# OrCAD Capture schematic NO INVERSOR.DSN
size A
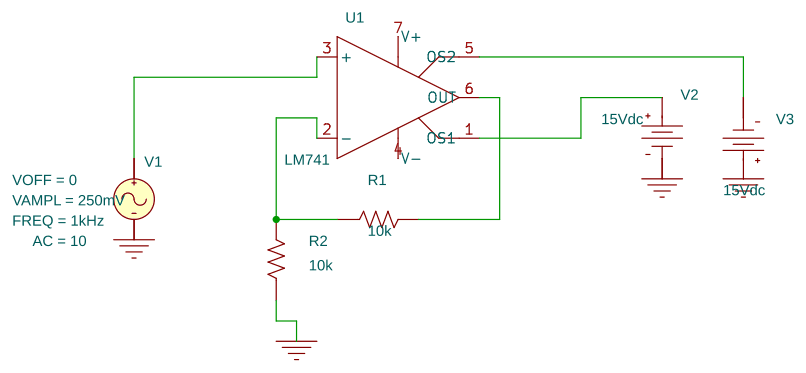
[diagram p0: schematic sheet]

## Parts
R1  10k  [AX/RC05]
R2  10k  [AX/RC05]
U1  LM741  [DIP.100/8/W.300/L.450]
V1  VSIN
V2  VDC
V3  VDC

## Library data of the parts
R1 R2 = r
U1 = LM741
V1 = VSIN: AC: 10; FREQ: 1kHz; VAMPL: 250mV; VOFF: 0
V2 V3 = VDC: DC: 15Vdc

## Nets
0: R2.1 V1.2(-) V2.1(-) V3.0(+)
V+: U1.7(V+)
V-: U1.4(V-)
N00232: U1.3(+) V1.1(+)
N00239: R1.1 R2.2 U1.2(-)
N00259: R1.2 U1.6(OUT)
N01273: U1.5(OS2) V3.1(-)
N01283: U1.1(OS1) V2.0(+)
